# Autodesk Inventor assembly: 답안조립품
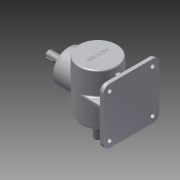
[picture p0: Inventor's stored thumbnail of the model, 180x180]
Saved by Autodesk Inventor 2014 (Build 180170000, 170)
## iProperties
Created: 2015-07
Part Number: 답안조립품
Document SubType Name: Assembly
Designer: sda
Author: sda
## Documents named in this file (14)
- C:\Users\sda\Desktop\450705V1021\답안조립품.iam
- C:\Users\sda\Desktop\450705V1021\본체.ipt
- C:\Users\sda\Desktop\450705V1021\커버.ipt
- C:\Users\sda\Desktop\450705V1021\베어링 6203.ipt
- C:\Users\sda\Desktop\450705V1021\오일실.ipt
- C:\Users\sda\Desktop\450705V1021\M4.ipt
- C:\Users\sda\Desktop\450705V1021\서브 베벨기어.ipt
- C:\Users\sda\Desktop\450705V1021\서브 축.ipt
- 서브 축.ipt
- C:\Users\sda\Desktop\450705V1021\키 4x4.ipt
- C:\Users\sda\Desktop\450705V1021\메인 베벨기어.ipt
- C:\Users\sda\Desktop\450705V1021\메인 축.ipt
- 메인 축.ipt
- C:\Users\sda\Desktop\450705V1021\키 5x5.ipt
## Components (8 placed, 1 different names)
1. M4:1
2. M4:3
3. M4:4
4. M4:5
5. M4:2
6. M4:6
7. M4:7
8. M4:8
